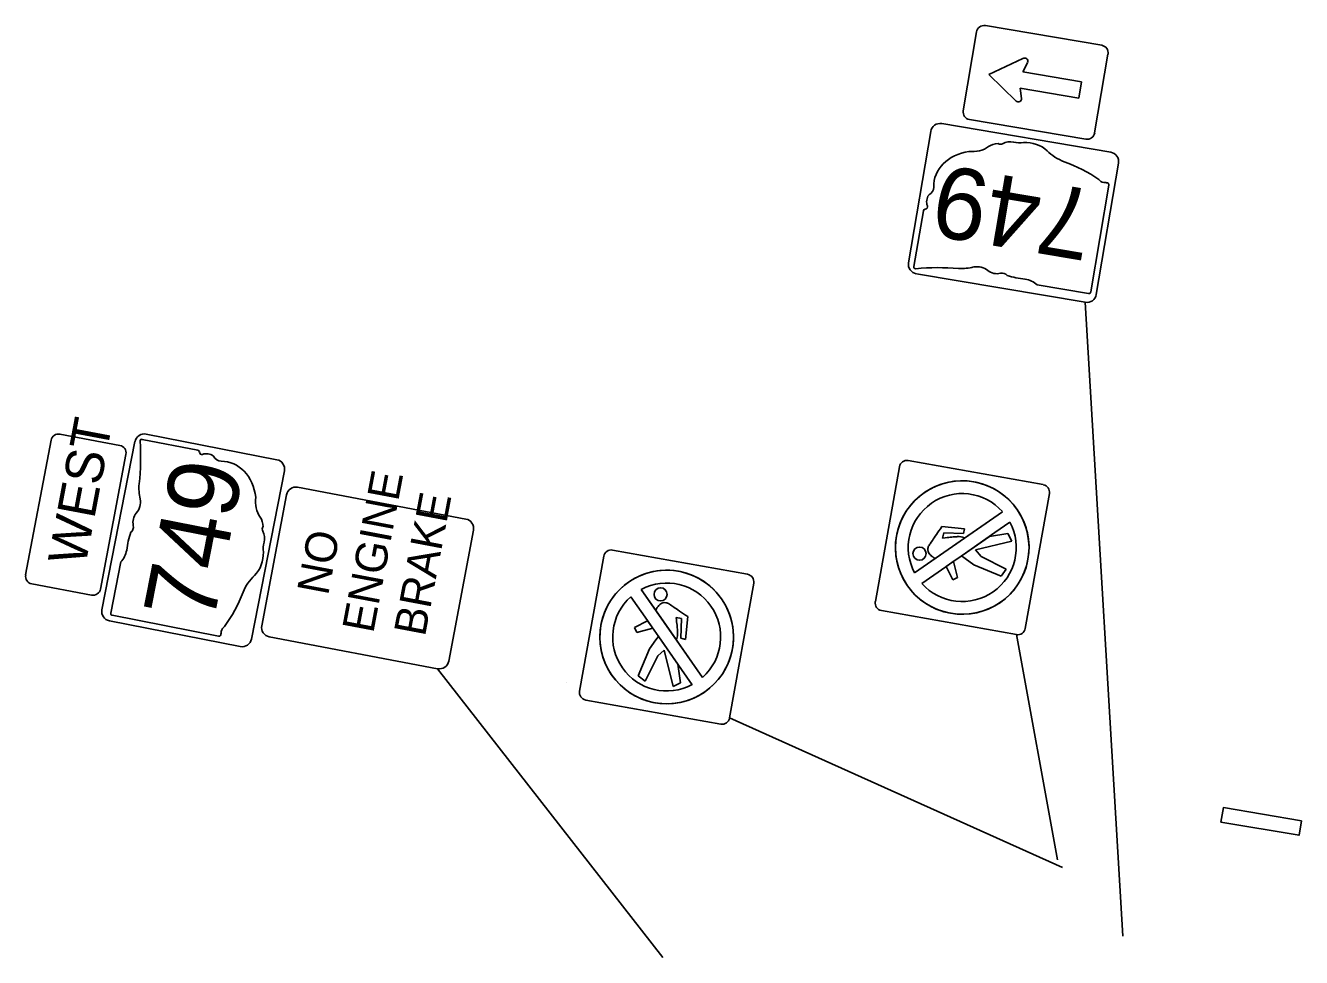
# Model space of a CAD drawing. Extents: x 1482113 to 1482447, y 365324 to 365634.
# Drawn here: x 1482112.8 to 1482280.3, y 365511.5 to 365633.9 of the extents above; entities that cross this region are included whole.
import ezdxf

# ---------------------------------------------------------------- set-up
doc = ezdxf.new("R2010")
doc.units = 0
for name, color, linetype in [('_CIVIL_CONSTRUCTION', 7, 'Continuous'), ('RS_Raster1', 7, 'Continuous'), ('RW_X_CL_500_Bearings', 7, 'Continuous')]:
    doc.layers.add(name, color=color, linetype=linetype)

msp = doc.modelspace()

# ---------------------------------------------------------------- linework, layer by layer
at = {"layer": '_CIVIL_CONSTRUCTION'}
msp.add_lwpolyline([(1482280.35, 365529.44), (1482270.09, 365531.18), (1482269.77, 365529.27), (1482280.03, 365527.54)], close=True, dxfattribs=at)
at = {"layer": 'RS_Raster1'}
for p, q in [((1482235.94, 365622.7), (1482237.69, 365633.06)), ((1482238.84, 365633.88), (1482254.12, 365631.29)), ((1482243.77, 365629.54), (1482239.28, 365627.46)), ((1482254.94, 365630.14), (1482253.19, 365619.79)), ((1482243.77, 365627.81), (1482244.38, 365629.01)), ((1482251.48, 365626.51), (1482243.77, 365627.81)), ((1482239.28, 365627.46), (1482242.88, 365623.97)), ((1482251.11, 365624.35), (1482251.48, 365626.51)), ((1482243.41, 365625.66), (1482251.11, 365624.35)), ((1482243.59, 365624.32), (1482243.41, 365625.66)), ((1482252.04, 365618.97), (1482236.76, 365621.55)), ((1482252.04, 365618.97), (1482252.04, 365618.97)), ((1482252.67, 365598.91), (1482255.04, 365612.94)), ((1482230.7, 365609.57), (1482229.46, 365602.23)), ((1482230.7, 365609.57), (1482230.7, 365609.57)), ((1482245.63, 365599.85), (1482252.4, 365598.71)), ((1482251.96, 365597.54), (1482256.88, 365514.29)), ((1482112.81, 365561.74), (1482116.16, 365579.43)), ((1482117.32, 365580.22), (1482125.18, 365578.74)), ((1482135.43, 365578.11), (1482128.12, 365579.54)), ((1482125.98, 365577.57), (1482122.64, 365559.88)), ((1482135.42, 365578.11), (1482135.43, 365578.11)), ((1482125.32, 365563.44), (1482124, 365556.7)), ((1482121.47, 365559.09), (1482113.61, 365560.57)), ((1482124.19, 365556.43), (1482138.16, 365553.69)), ((1482166.91, 365549.42), (1482196.48, 365511.49)), ((1482183.9, 365547.56), (1482183.9, 365547.56))]:
    msp.add_line(p, q, dxfattribs=at)
for points in [[(1482233.11, 365621.01), (1482255.3, 365617.26)], [(1482228.75, 365602.73), (1482231.67, 365619.98)], [(1482256.32, 365615.82), (1482253.4, 365598.56)], [(1482251.96, 365597.54), (1482229.78, 365601.29)], [(1482122.84, 365557.17), (1482127.17, 365579.25)], [(1482128.64, 365580.24), (1482145.81, 365576.87)], [(1482146.8, 365575.4), (1482142.46, 365553.32)], [(1482147.06, 365572.26), (1482143.81, 365555.06)], [(1482170.63, 365569.07), (1482148.52, 365573.25)], [(1482168.37, 365550.42), (1482171.62, 365567.61)], [(1482141, 365552.33), (1482123.82, 365555.71)], [(1482144.8, 365553.6), (1482166.91, 365549.42)]]:
    msp.add_lwpolyline(points, dxfattribs=at)
for centre, radius, start, end in [((1482238.67, 365632.89), 1, 80.4, 170.4), ((1482253.96, 365630.31), 1, 350.4, 80.4), ((1482244.01, 365629.2), 0.417, 333.1954, 125.4096), ((1482243.17, 365624.27), 0.417, 225.8112, 7.6046), ((1482236.92, 365622.54), 1, 170.4, 260.4), ((1482232.9, 365619.78), 1.25, 80.4, 170.4), ((1482252.21, 365619.95), 1, 260.4, 350.4), ((1482255.09, 365616.02), 1.25, 350.4, 80.4), ((1482229.98, 365602.52), 1.25, 170.4, 260.4), ((1482252.17, 365598.77), 1.25, 260.4, 350.4), ((1482117.14, 365579.24), 1, 79.3, 169.3), ((1482128.4, 365579.01), 1.25, 78.8891, 168.8891), ((1482125, 365577.76), 1, 349.3, 79.3), ((1482145.57, 365575.64), 1.25, 348.8891, 78.8891), ((1482148.29, 365572.02), 1.25, 79.3, 169.3), ((1482170.39, 365567.85), 1.25, 349.3, 79.3), ((1482113.8, 365561.55), 1, 169.3, 259.3), ((1482121.66, 365560.07), 1, 259.3, 349.3), ((1482124.06, 365556.93), 1.25, 168.8891, 258.8891), ((1482145.04, 365554.83), 1.25, 169.3, 259.3), ((1482141.24, 365553.56), 1.25, 258.8891, 348.8891), ((1482167.15, 365550.65), 1.25, 259.3, 349.3)]:
    msp.add_arc(centre, radius, start, end, dxfattribs=at)
for centre, major_axis, start_param, end_param in [((1482236.87, 365620.07), (-3.36, 0.57), 1.647645, 2.488434), ((1482240.69, 365616.77), (-1.98, 0.33), 4.937069, 5.64225), ((1482240.79, 365618.73), (-0.527, 0.089), 1.147584, 2.315152), ((1482242.26, 365617.09), (-1.87, 0.32), 4.691044, 5.507374), ((1482243.16, 365620.85), (-2.89, 0.49), 1.495662, 1.94098), ((1482244.37, 365615.65), (-3.51, 0.59), 4.026481, 4.996735), ((1482238.24, 365612.41), (-6.13, 1.04), 5.101752, 6.440018), ((1482251.27, 365620.06), (-5.54, 0.94), 0.823519, 1.323587), ((1482242.93, 365602.85), (-17.7, 2.99), 4.195997, 4.488961), ((1482230.3, 365612.8), (-1.74, 0.29), 2.387724, 3.262537), ((1482254.45, 365613.87), (-0.743, 0.126), 0.519207, 1.627899), ((1482254.5, 365611.59), (-2.06, 0.35), 4.665946, 4.897461), ((1482254.78, 365613.02), (-0.27, 0.046), 3.00124, 4.508301), ((1482233.54, 365610.6), (-2.39, 0.4), 5.934695, 6.695948), ((1482230.98, 365609.55), (-0.275, 0.047), 5.05454, 6.418171), ((1482230.85, 365610.1), (-0.398, 0.067), 1.883978, 3.671073), ((1482229.71, 365602.15), (-0.257, 0.044), 6.141152, 7.989035), ((1482234.52, 365582.05), (-24.51, 4.14), 4.814394, 5.042369), ((1482235.35, 365606), (-4.93, 0.83), 1.699011, 2.107814), ((1482237.86, 365600.69), (-1.87, 0.32), 4.081561, 5.145723), ((1482240.24, 365602.57), (-1.56, 0.26), 0.950623, 2.079405), ((1482241.07, 365600.77), (-0.749, 0.127), 3.836095, 5.185415), ((1482244.49, 365608.15), (-9.32, 1.58), 1.404758, 1.657858), ((1482243.75, 365598.49), (-2.6, 0.44), 4.042523, 4.731795), ((1482252.4, 365598.92), (-0.268, 0.045), 1.712693, 3.28349), ((1482107.82, 365575.02), (4.79, 24.39), 4.814394, 5.042369), ((1482128.04, 365579.29), (0.05, 0.256), 6.141152, 7.989035), ((1482135.4, 365577.83), (0.054, 0.274), 5.05454, 6.418171), ((1482135.95, 365577.94), (0.078, 0.396), 1.883978, 3.671073), ((1482136.38, 365575.24), (0.47, 2.38), 5.934695, 6.695948), ((1482138.66, 365578.42), (0.34, 1.73), 2.387724, 3.262537), ((1482138.07, 365570.5), (1.2, 6.1), 5.101752, 6.440018), ((1482131.73, 365573.56), (0.96, 4.91), 1.699011, 2.107814), ((1482126.36, 365571.19), (0.37, 1.86), 4.081561, 5.145723), ((1482145.76, 365571.66), (0.66, 3.34), 1.647645, 2.488434), ((1482128.18, 365568.76), (0.3, 1.55), 0.950623, 2.079405), ((1482142.36, 365567.93), (0.39, 1.97), 4.937069, 5.64225), ((1482133.64, 365564.36), (1.82, 9.28), 1.404758, 1.657858), ((1482126.35, 365567.98), (0.146, 0.746), 3.836095, 5.185415), ((1482144.32, 365567.78), (0.103, 0.525), 1.147584, 2.315152), ((1482142.64, 365566.36), (0.37, 1.86), 4.691044, 5.507374), ((1482146.37, 365565.36), (0.56, 2.87), 1.495662, 1.94098), ((1482124.01, 365565.36), (0.51, 2.58), 4.042523, 4.731795), ((1482141.15, 365564.29), (0.69, 3.5), 4.026481, 4.996735), ((1482145.37, 365557.27), (1.08, 5.51), 0.823519, 1.323587), ((1482128.39, 365566.06), (3.46, 17.61), 4.195997, 4.488961), ((1482124.21, 365556.7), (0.052, 0.266), 1.712693, 3.28349), ((1482138.24, 365553.95), (0.053, 0.269), 3.00124, 4.508301), ((1482136.82, 365554.27), (0.4, 2.05), 4.665946, 4.897461), ((1482139.1, 365554.25), (0.145, 0.74), 0.519207, 1.627899)]:
    msp.add_ellipse(centre, major_axis=major_axis, ratio=0.8, start_param=start_param, end_param=end_param, dxfattribs=at)
at = {"layer": 'RW_X_CL_500_Bearings'}
for p, q in [((1482229.55, 365561.99), (1482241.1, 365570.04)), ((1482233.13, 365568.11), (1482233.12, 365568.09)), ((1482233.13, 365568.11), (1482233.12, 365568.09)), ((1482236.11, 365567.81), (1482233.13, 365568.11)), ((1482236.11, 365567.81), (1482233.13, 365568.11)), ((1482233.23, 365566.56), (1482233.39, 365567.27)), ((1482233.23, 365566.56), (1482233.39, 365567.27)), ((1482233.39, 365567.27), (1482235.95, 365567.19)), ((1482233.39, 365567.27), (1482235.95, 365567.19)), ((1482235.95, 365567.19), (1482236.11, 365567.81)), ((1482235.95, 365567.19), (1482236.11, 365567.81)), ((1482232.39, 365563.97), (1482236.12, 365566.58)), ((1482239.36, 365566.79), (1482235.78, 365564.29)), ((1482237.53, 365565.02), (1482242.32, 365566.16)), ((1482237.53, 365565.02), (1482242.32, 365566.16)), ((1482241.81, 365567.16), (1482239.36, 365566.79)), ((1482241.81, 365567.16), (1482239.36, 365566.79)), ((1482242.32, 365566.16), (1482241.81, 365567.16)), ((1482242.32, 365566.16), (1482241.81, 365567.16)), ((1482232.27, 365563.89), (1482232.39, 365563.97)), ((1482235.78, 365564.29), (1482235.71, 365564.24)), ((1482235.71, 365564.24), (1482236.17, 365563.89)), ((1482235.71, 365564.24), (1482236.17, 365563.89)), ((1482236.17, 365563.89), (1482237.33, 365563.07)), ((1482236.17, 365563.89), (1482237.33, 365563.07)), ((1482238.29, 365564.16), (1482237.53, 365565.02)), ((1482238.29, 365564.16), (1482237.53, 365565.02)), ((1482241.58, 365562.51), (1482238.29, 365564.16)), ((1482241.58, 365562.51), (1482238.29, 365564.16)), ((1482233.69, 365562.83), (1482234.55, 365561.11)), ((1482233.69, 365562.83), (1482234.55, 365561.11)), ((1482234.65, 365563.5), (1482234.45, 365563.36)), ((1482235.2, 365561.4), (1482234.65, 365563.5)), ((1482235.2, 365561.4), (1482234.65, 365563.5)), ((1482237.33, 365563.07), (1482240.9, 365561.59)), ((1482237.33, 365563.07), (1482240.9, 365561.59)), ((1482240.9, 365561.59), (1482241.58, 365562.51)), ((1482240.9, 365561.59), (1482241.58, 365562.51)), ((1482234.55, 365561.11), (1482235.2, 365561.4)), ((1482234.55, 365561.11), (1482235.2, 365561.4)), ((1482193.65, 365559.84), (1482201.7, 365548.28)), ((1482194.49, 365555.7), (1482192.77, 365554.83)), ((1482194.49, 365555.69), (1482192.77, 365554.83)), ((1482195.55, 365557.12), (1482195.63, 365557)), ((1482195.63, 365557), (1482198.24, 365553.26)), ((1482198.22, 365556.15), (1482198.93, 365556)), ((1482198.22, 365556.15), (1482198.93, 365556)), ((1482198.93, 365556), (1482198.85, 365553.44)), ((1482198.93, 365556), (1482198.85, 365553.44)), ((1482199.47, 365553.27), (1482199.77, 365556.26)), ((1482199.47, 365553.27), (1482199.77, 365556.26)), ((1482199.77, 365556.26), (1482199.75, 365556.26)), ((1482199.77, 365556.26), (1482199.75, 365556.26)), ((1482192.77, 365554.83), (1482193.06, 365554.18)), ((1482192.77, 365554.83), (1482193.06, 365554.18)), ((1482193.06, 365554.18), (1482195.16, 365554.74)), ((1482193.06, 365554.18), (1482195.16, 365554.74)), ((1482195.16, 365554.74), (1482195.02, 365554.93)), ((1482242.92, 365553.9), (1482248.3, 365524.33)), ((1482195.55, 365553.22), (1482194.73, 365552.05)), ((1482195.55, 365553.22), (1482194.73, 365552.05)), ((1482195.9, 365553.67), (1482195.55, 365553.22)), ((1482195.9, 365553.67), (1482195.55, 365553.22)), ((1482195.95, 365553.6), (1482195.9, 365553.67)), ((1482198.45, 365550.02), (1482195.95, 365553.6)), ((1482198.85, 365553.44), (1482199.47, 365553.27)), ((1482198.85, 365553.44), (1482199.47, 365553.27)), ((1482194.73, 365552.05), (1482193.25, 365548.48)), ((1482194.73, 365552.05), (1482193.25, 365548.48)), ((1482194.17, 365547.8), (1482195.82, 365551.09)), ((1482194.17, 365547.8), (1482195.82, 365551.09)), ((1482195.82, 365551.09), (1482196.68, 365551.85)), ((1482195.82, 365551.09), (1482196.68, 365551.85)), ((1482196.68, 365551.85), (1482197.83, 365547.07)), ((1482196.68, 365551.85), (1482197.83, 365547.07)), ((1482198.82, 365547.57), (1482198.45, 365550.02)), ((1482198.82, 365547.57), (1482198.45, 365550.02)), ((1482193.25, 365548.48), (1482194.17, 365547.8)), ((1482193.25, 365548.48), (1482194.17, 365547.8)), ((1482197.83, 365547.07), (1482198.82, 365547.57)), ((1482197.83, 365547.07), (1482198.82, 365547.57)), ((1482205.25, 365542.95), (1482248.95, 365523.33))]:
    msp.add_line(p, q, dxfattribs=at)
for points in [[(1482227.56, 365575.95), (1482224.39, 365558.23)], [(1482246.44, 365573.59), (1482228.72, 365576.75)], [(1482244.08, 365554.71), (1482247.24, 365572.43)], [(1482241.1, 365570.04), (1482236.52, 365566.85), (1482236.52, 365566.85), (1482236.52, 365566.85), (1482232.39, 365563.97), (1482232.39, 365563.97)], [(1482234.45, 365563.36), (1482235.78, 365564.29), (1482240.08, 365567.29), (1482242.06, 365568.67)], [(1482188.73, 365564.18), (1482185.56, 365546.47)], [(1482207.61, 365561.83), (1482189.89, 365564.99)], [(1482232.39, 365563.97), (1482229.55, 365561.99)], [(1482232.39, 365563.97), (1482232.39, 365563.97)], [(1482230.51, 365560.61), (1482233.65, 365562.8), (1482234.45, 365563.37), (1482234.45, 365563.36)], [(1482234.45, 365563.36), (1482233.69, 365562.83), (1482233.69, 365562.83)], [(1482205.25, 365542.95), (1482208.42, 365560.67)], [(1482192.27, 365558.87), (1482194.46, 365555.73), (1482195.03, 365554.93), (1482195.02, 365554.93)], [(1482195.63, 365557), (1482193.65, 365559.84)], [(1482195.02, 365554.93), (1482194.49, 365555.69), (1482194.49, 365555.69)], [(1482201.7, 365548.28), (1482198.51, 365552.87), (1482198.51, 365552.87), (1482198.51, 365552.87), (1482195.63, 365557), (1482195.63, 365556.99)], [(1482195.63, 365557), (1482195.63, 365557)], [(1482225.2, 365557.07), (1482242.92, 365553.9)], [(1482195.02, 365554.93), (1482195.95, 365553.6), (1482198.95, 365549.3), (1482200.33, 365547.32)], [(1482186.37, 365545.3), (1482204.09, 365542.14)]]:
    msp.add_lwpolyline(points, dxfattribs=at)
for centre, radius in [((1482235.8, 365565.33), 8.77), ((1482230.2, 365564.53), 0.864), ((1482196.99, 365553.58), 8.77), ((1482196.19, 365559.18), 0.864)]:
    msp.add_circle(centre, radius, dxfattribs=at)
for centre, radius, start, end in [((1482228.54, 365575.77), 1, 79.8676, 169.8676), ((1482235.8, 365565.33), 8.77, 79.8676, 259.8676), ((1482235.8, 365565.33), 8.77, 259.8676, 79.8676), ((1482235.8, 365565.33), 7.09, 41.6867, 208.0389), ((1482235.8, 365565.33), 7.09, 41.6867, 208.0389), ((1482246.26, 365572.6), 1, 349.8676, 79.8676), ((1482235.8, 365565.33), 7.09, 221.7155, 28.1155), ((1482235.8, 365565.33), 7.09, 221.7155, 28.1155), ((1482189.71, 365564.01), 1, 79.8676, 169.8676), ((1482233.53, 365565), 1.54, 221.9428, 221.9959), ((1482196.99, 365553.58), 8.77, 349.8676, 169.8676), ((1482196.99, 365553.58), 7.09, 311.6867, 118.0389), ((1482196.99, 365553.58), 7.09, 311.6867, 118.0389), ((1482207.43, 365560.84), 1, 349.8676, 79.8676), ((1482196.99, 365553.58), 7.09, 131.7155, 298.1155), ((1482196.99, 365553.58), 7.09, 131.7155, 298.1155), ((1482225.37, 365558.05), 1, 169.8676, 259.8676), ((1482196.66, 365555.85), 1.54, 131.9428, 131.9959), ((1482196.99, 365553.58), 8.77, 169.8676, 349.8676), ((1482243.09, 365554.88), 1, 259.8676, 349.8676), ((1482186.54, 365546.29), 1, 169.8676, 259.8676), ((1482204.26, 365543.12), 1, 259.8676, 349.8676)]:
    msp.add_arc(centre, radius, start, end, dxfattribs=at)
for points in [[(1482233.12, 365568.09), (1482232.59, 365567.29), (1482231.72, 365566.03), (1482231.4, 365565.57), (1482231.34, 365565.41), (1482231.31, 365565.25), (1482231.24, 365564.85), (1482231.62, 365564.27), (1482232.02, 365564.04), (1482232.27, 365563.89)], [(1482233.12, 365568.09), (1482232.59, 365567.29), (1482231.72, 365566.03), (1482231.4, 365565.57), (1482231.34, 365565.41), (1482231.31, 365565.25), (1482231.24, 365564.85), (1482231.62, 365564.27), (1482232.02, 365564.04), (1482232.27, 365563.89)], [(1482236.12, 365566.58), (1482236.06, 365566.62), (1482235.87, 365566.72), (1482235.41, 365566.77), (1482234.99, 365566.76), (1482234.24, 365566.69), (1482233.72, 365566.63), (1482233.23, 365566.56)], [(1482236.12, 365566.58), (1482236.06, 365566.62), (1482235.87, 365566.72), (1482235.41, 365566.77), (1482234.99, 365566.76), (1482234.24, 365566.69), (1482233.72, 365566.63), (1482233.23, 365566.56)], [(1482199.75, 365556.26), (1482198.95, 365556.8), (1482197.69, 365557.66), (1482197.24, 365557.98), (1482197.08, 365558.05), (1482196.91, 365558.08), (1482196.51, 365558.15), (1482195.94, 365557.77), (1482195.7, 365557.36), (1482195.55, 365557.12)], [(1482199.75, 365556.26), (1482198.95, 365556.8), (1482197.69, 365557.66), (1482197.24, 365557.98), (1482197.08, 365558.05), (1482196.91, 365558.08), (1482196.51, 365558.15), (1482195.94, 365557.77), (1482195.7, 365557.36), (1482195.55, 365557.12)], [(1482198.24, 365553.26), (1482198.28, 365553.32), (1482198.38, 365553.51), (1482198.43, 365553.97), (1482198.42, 365554.39), (1482198.35, 365555.14), (1482198.29, 365555.66), (1482198.22, 365556.15)], [(1482198.24, 365553.26), (1482198.28, 365553.32), (1482198.38, 365553.51), (1482198.43, 365553.97), (1482198.42, 365554.39), (1482198.35, 365555.14), (1482198.29, 365555.66), (1482198.22, 365556.15)]]:
    msp.add_open_spline(points, degree=3, dxfattribs=at)

# ---------------------------------------------------------------- texts
at = {"layer": 'RS_Raster1'}
for s, height, rotation, p in [('749', 9.375, 170.4, (1482253.59, 365612.17)), ('WEST', 5, 79.3, (1482120.64, 365562.78)), ('749', 9.375, 78.8891, (1482137.42, 365555.16)), ('ENGINE', 4.165, 79.3, (1482158.45, 365553.97)), ('BRAKE', 4.165, 79.3, (1482165.24, 365553.53)), ('NO', 4.165, 79.3, (1482152.52, 365558.93))]:
    msp.add_text(s, height=height, rotation=rotation, dxfattribs=at).set_placement(p)

doc.saveas('drawing.dxf')
